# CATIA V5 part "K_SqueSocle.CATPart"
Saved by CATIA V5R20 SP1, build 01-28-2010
Part number: squelette_socle
Publications: "Point.1", "Point.2", "Point.3", "Point.4", "Point.5", "Point.6", "Point.7", "Point.8", "Droite.1", "Droite.2", "Droite.3", "Droite.4", "Plan.1", "Droite.5", "Droite.6", "Droite.7", "Droite.8"
Bounding box of the stored display mesh (mm): x 0 to 0, y -32 to 20, z 0 to 50
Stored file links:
  G:\Khaled_CFAO_2011\ST2M\ST2M_GR2\gcausse\Khaled\CAD_ThinkMotion\K_SqueSocle.CATPart
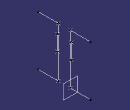
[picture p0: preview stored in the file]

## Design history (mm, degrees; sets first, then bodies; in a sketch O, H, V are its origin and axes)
Set1
  Point1: (0, 0, 0)
  Point2: (0, 0, 50)
  Point3: (0, -12, 50)
  Point4: (0, -12, 0)
  Point5: (0, -13, 40)
  Point6: (0, -13, 25)
  Point7: (0, 1, 25)
  Point8: (0, 1, 40)
  Line1: type PtPt, FirstPoint Point2, SecondPoint Point1
  Line2: type PtPt, FirstPoint Point3, SecondPoint Point4
  Line3: type PtPt, FirstPoint Point8, SecondPoint Point7
  Line4: type PtPt, FirstPoint Point5, SecondPoint Point6
  Plane1: type Offset, RefPlane zx-plane, Offset 0
  Line5: type PtDir, RefPoint Point3, Direction Plane1, Start 0, End 20
  Line6: type PtDir, RefPoint Point2, Direction Plane1, Start 0, End 20
  Line7: type PtDir, RefPoint Point1, Direction Plane1, Start 0, End 20
  Line8: type PtDir, RefPoint Point4, Direction Plane1, Start 0, End 20
Body1 (main body)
